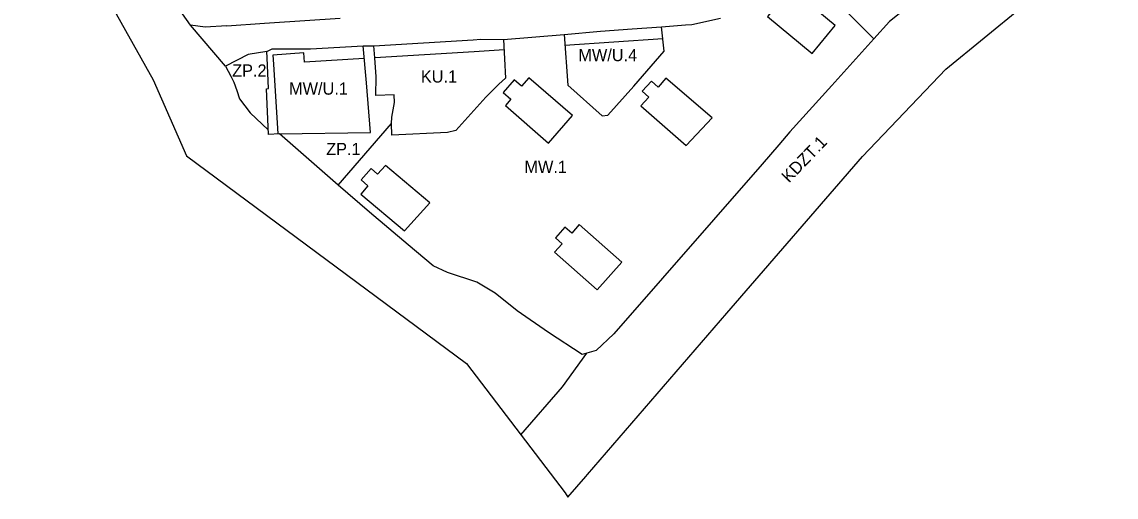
# Model space of a CAD drawing. Extents: x 7426178 to 7427732, y 5548847 to 5550287.
# Drawn here: x 7427012.7 to 7427416.4, y 5548847.4 to 5549022.7 of the extents above; entities that cross this region are included whole.
import ezdxf

# ---------------------------------------------------------------- set-up
doc = ezdxf.new("R2010")
doc.units = 0
for name, color, linetype in [('linie_rozgraniczajace', 7, 'Continuous'), ('linie_zabudowy_nieprzekraczalne', 7, 'Continuous'), ('linie_zabudowy_obowiazujace', 7, 'Continuous'), ('oznaczenia_przeznaczen', 7, 'Continuous')]:
    doc.layers.add(name, color=color, linetype=linetype)

msp = doc.modelspace()

# ---------------------------------------------------------------- linework, layer by layer
at = {"layer": 'linie_rozgraniczajace'}
for p, q in [((7427087.87, 5549006.41), (7427074.88, 5549021.46)), ((7427129.41, 5548962.49), (7427149.1, 5548985.21)), ((7427214.1, 5548847.4), (7427220.71, 5548855.04)), ((7427213.08, 5548849.03), (7427214.1, 5548847.4))]:
    msp.add_line(p, q, dxfattribs=at)
for points in [[(7426806.41, 5549611.72), (7426845.02, 5549569.73), (7426883.5, 5549515.53), (7426907.93, 5549461.17), (7426932.17, 5549384.03), (7426948.93, 5549331.51), (7426962.26, 5549289.73), (7427024.27, 5549067.18), (7427061.13, 5549001.37), (7427073.43, 5548973.27), (7427176.69, 5548896.63), (7427213.08, 5548849.03)], [(7427399.19, 5549074.01), (7427392.13, 5549065.52), (7427390.09, 5549063.5), (7427384.02, 5549059.44), (7427369.94, 5549050.26), (7427353.86, 5549039.49), (7427342.52, 5549030.44), (7427339.32, 5549028.06), (7427332.77, 5549022.84), (7427327.03, 5549016.4), (7427298.27, 5549045.42)], [(7427088.36, 5549021.31), (7427080.37, 5549020.78), (7427074.88, 5549021.46), (7427071.9, 5549025.67), (7427060.27, 5549041.15), (7427056.72, 5549046.74), (7427051.09, 5549060.09), (7427049.64, 5549064.12), (7427046.96, 5549072.63)], [(7427322.79, 5548973.01), (7427353.54, 5549005.3), (7427381.87, 5549028.34), (7427390.86, 5549033.31), (7427416.4, 5549047.44)], [(7427088.36, 5549021.31), (7427102.25, 5549022.19), (7427104.06, 5549022.31), (7427130.16, 5549024.09)], [(7427190.38, 5549016.21), (7427191.08, 5549001.97), (7427188.71, 5548999.69), (7427183.81, 5548994.95), (7427172.8, 5548982.62), (7427169.73, 5548981.88), (7427149.2, 5548980.87), (7427149.1, 5548985.21), (7427149.21, 5548987.55), (7427150.19, 5548992.98), (7427150.06, 5548995.84), (7427143.22, 5548995.53), (7427143.37, 5549002.39), (7427142.88, 5549009.39), (7427142.56, 5549013.91), (7427179.17, 5549016.12), (7427182.05, 5549016.3), (7427190.38, 5549016.21), (7427212.75, 5549018.06), (7427226.2, 5549019.27), (7427237.89, 5549020.11), (7427248.61, 5549020.87), (7427257.53, 5549021.61), (7427259.91, 5549021.73), (7427270.42, 5549024.12)], [(7427212.75, 5549018.06), (7427214.1, 5548999.33), (7427226.84, 5548988.02), (7427228.81, 5548988.27), (7427238.41, 5548998.99), (7427249.69, 5549011.9), (7427248.61, 5549020.87)], [(7427103.08, 5549011.74), (7427104.98, 5549012.75), (7427119.2, 5549012.72), (7427138.6, 5549013.89), (7427142.56, 5549013.91)], [(7427327.03, 5549016.4), (7427311.55, 5548999.26), (7427296.07, 5548982.12), (7427292.02, 5548977.39), (7427285.81, 5548970.16), (7427231.09, 5548907.59), (7427224.55, 5548901.5), (7427219.37, 5548900.01), (7427206.94, 5548908.08), (7427195.42, 5548916.12), (7427187.25, 5548922.62), (7427180.52, 5548926.66), (7427169.69, 5548930.29), (7427164.42, 5548932.74), (7427155.22, 5548940.52), (7427140.92, 5548952.55), (7427129.41, 5548962.49), (7427107.78, 5548981.4)], [(7427107.78, 5548981.4), (7427141.35, 5548981.95), (7427139.85, 5549000.17), (7427138.6, 5549013.89)], [(7427103.08, 5549011.74), (7427096.12, 5549010.62), (7427087.87, 5549006.41), (7427089.79, 5549002.65), (7427090.93, 5549000.42), (7427091.97, 5548997.35), (7427093.01, 5548994.27), (7427096.86, 5548989.21), (7427103.57, 5548982.93)], [(7427107.78, 5548981.4), (7427103.64, 5548981.13), (7427102.96, 5548998), (7427103.64, 5548998.08), (7427103.22, 5549009.42), (7427103.08, 5549011.74)], [(7427220.71, 5548855.04), (7427221.31, 5548855.74), (7427272.83, 5548915.27), (7427322.79, 5548973.01)], [(7427196.76, 5548870.38), (7427212.14, 5548888.09), (7427221.16, 5548900.53)]]:
    msp.add_lwpolyline(points, dxfattribs=at)
at = {"layer": 'linie_zabudowy_nieprzekraczalne'}
for points in [[(7427139.03, 5549009.15), (7427116.95, 5549007.79), (7427116.72, 5549011.23), (7427105.32, 5549010.45), (7427105.55, 5549007.09), (7427107.16, 5548981.36)], [(7427190.57, 5549012.41), (7427179.59, 5549011.65), (7427142.88, 5549009.39)]]:
    msp.add_lwpolyline(points, dxfattribs=at)
at = {"layer": 'linie_zabudowy_obowiazujace'}
for points in [[(7427296.4, 5549034.97), (7427293.76, 5549031.79), (7427291.29, 5549033.85), (7427288.01, 5549029.9), (7427290.45, 5549027.87), (7427287.83, 5549024.71), (7427304.26, 5549011.07), (7427312.8, 5549021.35), (7427296.4, 5549034.97)], [(7427249.14, 5549016.47), (7427213.05, 5549013.97)], [(7427199.73, 5549002.08), (7427197, 5548998.95), (7427194.3, 5549001.3), (7427190.23, 5548996.61), (7427193.08, 5548994.14), (7427191.07, 5548991.82), (7427207, 5548977.99), (7427215.8, 5548988.14), (7427199.73, 5549002.08)], [(7427250.33, 5549001.89), (7427247.41, 5548998.66), (7427244.98, 5549000.86), (7427241.59, 5548997.12), (7427244.02, 5548994.92), (7427241.1, 5548991.69), (7427257.73, 5548977.12), (7427267.35, 5548987.3), (7427250.33, 5549001.89)], [(7427163.23, 5548956), (7427146.81, 5548969.78), (7427143.87, 5548966.5), (7427141.52, 5548968.58), (7427137.9, 5548964.4), (7427140.34, 5548962.22), (7427137.78, 5548959.19), (7427153.85, 5548945.6), (7427163.23, 5548956)], [(7427215.53, 5548944.78), (7427213.01, 5548947.02), (7427209.53, 5548943.1), (7427212.02, 5548940.88), (7427209.24, 5548937.74), (7427224.89, 5548923.83), (7427233.99, 5548934.08), (7427218.35, 5548947.96), (7427215.53, 5548944.78)]]:
    msp.add_lwpolyline(points, dxfattribs=at)

# ---------------------------------------------------------------- texts
at = {"layer": 'oznaczenia_przeznaczen'}
for s, p in [('MW/U.4', (7427217.98, 5549008.21)), ('ZP.2', (7427090.25, 5549002.52)), ('KU.1', (7427159.88, 5549000.32)), ('MW/U.1', (7427111.26, 5548995.85)), ('ZP.1', (7427124.94, 5548973.56)), ('MW.1', (7427198.08, 5548966.98))]:
    msp.add_text(s, height=4.5, dxfattribs=at).set_placement(p)
msp.add_text('KDZT.1', height=4.5, rotation=46.1491, dxfattribs=at).set_placement((7427295.72, 5548963.07))

doc.saveas('drawing.dxf')
